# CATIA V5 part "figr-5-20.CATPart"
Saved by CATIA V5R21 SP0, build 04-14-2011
Part number: Part1
Bounding box of the stored display mesh (mm): x -89.73 to 98.105, y -54.237 to 64.207, z 0 to 103
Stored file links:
  D:\CATIA V5R21 E-RESOURCES\CATIA-V5R21\catia-v5r21-prt\c05-catia-v5r20-prt\catia-v5r21-figr-5-20.CATPart
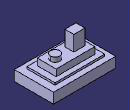
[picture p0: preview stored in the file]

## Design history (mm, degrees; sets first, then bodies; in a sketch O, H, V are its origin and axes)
Body1 (main body)
  Sketch1 on xy-plane, origin (0, 0, 0), H (1, 0, 0), V (0, 1, 0)
    line L1 (-89.7304, 64.2071) -> (98.1053, 64.2071)
    line L2 (98.1053, 64.2071) -> (98.1053, -54.2371)
    line L3 (98.1053, -54.2371) -> (-89.7304, -54.2371)
    line L4 (-89.7304, -54.2371) -> (-89.7304, 64.2071)
    line L5 (-72.4817, 47.8756) -> (77.1251, 47.8756)
    line L6 (77.1251, 47.8756) -> (77.1251, -36.7263)
    line L7 (77.1251, -36.7263) -> (-72.4817, -36.7263)
    line L8 (-72.4817, -36.7263) -> (-72.4817, 47.8756)
    line L9 (-57.1864, 33.5363) -> (59.44, 33.5363)
    line L10 (59.44, 33.5363) -> (59.44, -23.821)
    line L11 (59.44, -23.821) -> (-57.1864, -23.821)
    line L12 (-57.1864, -23.821) -> (-57.1864, 33.5363)
    circle A1 centre (34.1072, 5.3356) radius 13.9353
    line L13 (-44.759, 16.3291) -> (-11.3006, 16.3291)
    line L14 (-11.3006, 16.3291) -> (-11.3006, -10.9156)
    line L15 (-11.3006, -10.9156) -> (-44.759, -10.9156)
    line L16 (-44.759, -10.9156) -> (-44.759, 16.3291)
    horizontal: L1 H, L3 H, L5 H, L7 H, L9 H, L11 H, L13 H, L15 H
    vertical: L4 V, L6 V, L8 V, L10 V, L12 V, L14 V, L16 V
  MultiPad1: profile Sketch1, domains (length 103; length 57; length 0 / length -37; length 31; length 71)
